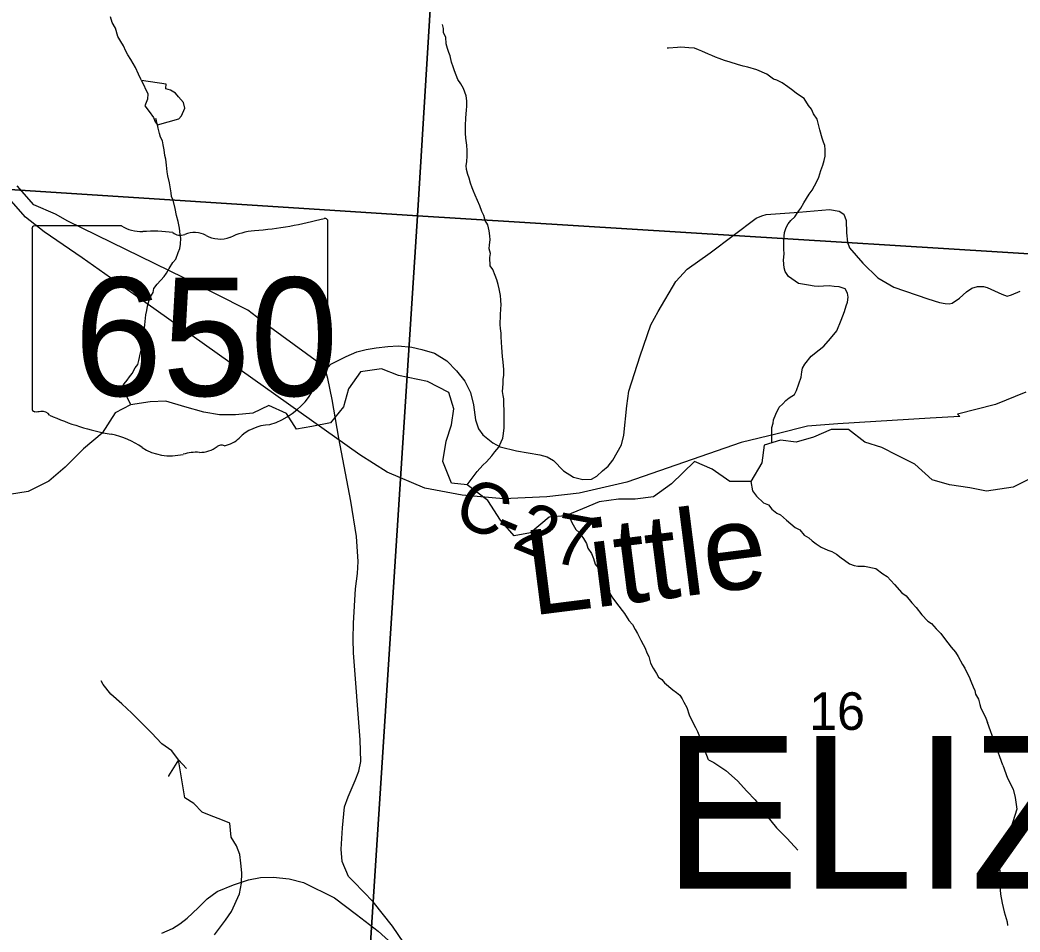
# Model space of a CAD drawing. Extents: x 0 to 82.7, y -0.2 to 22.
# Drawn here: x 4.26 to 5.374, y 16.567 to 17.584 of the extents above; entities that cross this region are included whole.
import ezdxf

# ---------------------------------------------------------------- set-up
doc = ezdxf.new("R2010")
doc.units = 0
for name, color, linetype in [('GM_X_County_Road', 7, 'Continuous'), ('GM_X_County_Road_Text', 7, 'Continuous'), ('GM_X_Minor_Lake', 7, 'Continuous'), ('GM_X_Minor_River', 7, 'Continuous'), ('GM_X_Minor_River_Text', 7, 'Continuous'), ('GM_X_Rail_Line', 7, 'Continuous'), ('GM_X_Section', 7, 'Continuous'), ('GM_X_Section_Text', 7, 'Continuous'), ('GM_X_State_Location', 7, 'Continuous'), ('GM_X_State_Route', 7, 'Continuous'), ('GM_X_State_Shield', 7, 'Continuous'), ('GM_X_Township_Text', 7, 'Continuous')]:
    doc.layers.add(name, color=color, linetype=linetype)

msp = doc.modelspace()

# ---------------------------------------------------------------- linework, layer by layer
at = {"layer": 'GM_X_County_Road'}
for points in [[(4.6002, 17.1934), (4.6062, 17.2003), (4.6231, 17.2085), (4.635, 17.2138), (4.6454, 17.2164), (4.6567, 17.2184), (4.6696, 17.2199), (4.681, 17.2204), (4.6965, 17.2189), (4.7075, 17.2166), (4.7217, 17.2124), (4.7354, 17.2039), (4.7463, 17.1927), (4.7554, 17.181), (4.7618, 17.1684), (4.765, 17.1547), (4.7674, 17.138), (4.7706, 17.128), (4.7756, 17.1213), (4.7867, 17.1125), (4.7946, 17.1081), (4.813, 17.1037), (4.8391, 17.099), (4.847, 17.0967), (4.8543, 17.0926), (4.8655, 17.0814), (4.8763, 17.0741), (4.8868, 17.0715), (4.8965, 17.0721), (4.9026, 17.0753), (4.9088, 17.0812), (4.9152, 17.0864), (4.9202, 17.0932), (4.9299, 17.1101), (4.9325, 17.121), (4.9357, 17.1538), (4.9381, 17.1702), (4.9506, 17.2093), (4.9625, 17.2439), (4.9707, 17.2587), (4.9905, 17.2923), (5.003, 17.3059), (5.0288, 17.3243), (5.08, 17.3628), (5.0862, 17.3654), (5.0909, 17.3669), (5.1274, 17.3695), (5.1617, 17.3726), (5.1723, 17.3708), (5.1775, 17.3672), (5.1801, 17.3604), (5.1806, 17.3464), (5.1816, 17.3361), (5.1839, 17.3298), (5.1987, 17.3125), (5.2156, 17.2964), (5.2332, 17.2858), (5.2712, 17.2731), (5.2842, 17.2688), (5.2905, 17.2677), (5.2948, 17.2673), (5.2981, 17.2682), (5.3063, 17.2736), (5.3143, 17.2806), (5.3202, 17.2848), (5.3266, 17.2865), (5.333, 17.2866), (5.3372, 17.2855), (5.3535, 17.278), (5.3594, 17.2759), (5.3644, 17.2773), (5.374, 17.2815)], [(4.4181, 16.5662), (4.4297, 16.5713), (4.4381, 16.5764), (4.4461, 16.5827), (4.4583, 16.5942), (4.4685, 16.6043), (4.4796, 16.6125), (4.4976, 16.6198), (4.5143, 16.6255), (4.528, 16.6281), (4.5421, 16.6283), (4.5599, 16.6266), (4.5758, 16.6226), (4.6103, 16.6054), (4.6347, 16.587), (4.6588, 16.5683), (4.6783, 16.5508)]]:
    msp.add_lwpolyline(points, dxfattribs=at)
at = {"layer": 'GM_X_Minor_Lake'}
for points in [[(4.3952, 17.5163), (4.4023, 17.5014), (4.4019, 17.4953), (4.3992, 17.4881), (4.4037, 17.4816), (4.4086, 17.4751), (4.4104, 17.4702), (4.4131, 17.4669)], [(4.4131, 17.4669), (4.437, 17.4734), (4.44, 17.4768), (4.4435, 17.4855), (4.442, 17.4916), (4.4364, 17.4981), (4.433, 17.5023), (4.4277, 17.5054), (4.4224, 17.5069), (4.4224, 17.5077), (4.4228, 17.5122), (4.3952, 17.5163)]]:
    msp.add_lwpolyline(points, dxfattribs=at)
at = {"layer": 'GM_X_Minor_River'}
for points in [[(4.3952, 17.5163), (4.3947, 17.5176), (4.3921, 17.5234), (4.3888, 17.5306), (4.3836, 17.5398), (4.3799, 17.5448), (4.378, 17.549), (4.3754, 17.5547), (4.3721, 17.5597), (4.3691, 17.5654), (4.3662, 17.5746), (4.3628, 17.5807), (4.3606, 17.5872)], [(4.7581, 17.0655), (4.7691, 17.0805), (4.7756, 17.0876), (4.7794, 17.0914), (4.7856, 17.0981), (4.789, 17.1023), (4.7933, 17.1075), (4.796, 17.1136), (4.7979, 17.1177), (4.7984, 17.1227), (4.7992, 17.1291), (4.7994, 17.1481), (4.7988, 17.1561), (4.7988, 17.1614), (4.7981, 17.1652), (4.7974, 17.1698), (4.7983, 17.1781), (4.7983, 17.1831), (4.7988, 17.188), (4.7988, 17.1941), (4.7982, 17.2025), (4.7975, 17.2085), (4.7965, 17.2188), (4.7958, 17.2306), (4.7959, 17.2348), (4.7952, 17.2397), (4.7949, 17.2443), (4.795, 17.2549), (4.7954, 17.2621), (4.7959, 17.2659), (4.7955, 17.2716), (4.7952, 17.2766), (4.7938, 17.2842), (4.7927, 17.2888), (4.7909, 17.2941), (4.7894, 17.2991), (4.7868, 17.3056), (4.7838, 17.3098), (4.7832, 17.3189), (4.784, 17.3235), (4.7825, 17.3288), (4.783, 17.333), (4.7838, 17.3387), (4.7831, 17.3432), (4.7824, 17.3486), (4.781, 17.3554), (4.778, 17.3604), (4.7765, 17.3657), (4.7743, 17.3703), (4.7721, 17.3764), (4.7669, 17.3886), (4.7651, 17.3928), (4.7636, 17.3967), (4.7618, 17.402), (4.7603, 17.4073), (4.7588, 17.4115), (4.7574, 17.4169), (4.7571, 17.4214), (4.7575, 17.4256), (4.7579, 17.4321), (4.758, 17.4382), (4.7577, 17.4442), (4.7567, 17.4518), (4.756, 17.4576), (4.7561, 17.4659), (4.7565, 17.4743), (4.7574, 17.4834), (4.7578, 17.4872), (4.7575, 17.4936), (4.7568, 17.4993), (4.7553, 17.5032), (4.7539, 17.5074), (4.7509, 17.5127), (4.7475, 17.5173), (4.7457, 17.5223), (4.7439, 17.5269), (4.7424, 17.5314), (4.7406, 17.5368), (4.7391, 17.5436), (4.7376, 17.5475), (4.7362, 17.552), (4.7347, 17.557), (4.7341, 17.5646), (4.7318, 17.5692), (4.7315, 17.5741), (4.7304, 17.5787)], [(5.0974, 17.1126), (5.0974, 17.1295), (5.099, 17.1344), (5.0994, 17.1382), (5.1017, 17.1443), (5.1056, 17.1522), (5.1095, 17.1559), (5.1129, 17.1597), (5.1168, 17.1627), (5.1225, 17.1664), (5.1248, 17.1709), (5.1299, 17.1857), (5.1307, 17.1914), (5.1316, 17.1956), (5.1343, 17.2001), (5.1412, 17.2091), (5.15, 17.2162), (5.1554, 17.2203), (5.1627, 17.2286), (5.1696, 17.2372), (5.1747, 17.249), (5.1782, 17.2588), (5.1802, 17.2652), (5.1817, 17.2694), (5.1822, 17.2747), (5.1815, 17.2793), (5.1789, 17.2839), (5.1724, 17.2862), (5.1667, 17.2867), (5.1611, 17.2875), (5.155, 17.2872), (5.1497, 17.2865), (5.1444, 17.287), (5.1383, 17.2882), (5.127, 17.2902), (5.1232, 17.2925), (5.116, 17.298), (5.1123, 17.3033), (5.1112, 17.3075), (5.1102, 17.3159), (5.111, 17.3231), (5.1107, 17.3284), (5.1108, 17.3387), (5.1113, 17.3467), (5.1133, 17.3523), (5.1156, 17.3565), (5.1187, 17.3602), (5.1229, 17.3644), (5.1264, 17.3696), (5.1298, 17.3741), (5.1329, 17.3798), (5.1391, 17.3896), (5.1422, 17.3941), (5.1449, 17.3987), (5.1476, 17.4036), (5.1496, 17.4085), (5.1519, 17.416), (5.1543, 17.4217), (5.1555, 17.427), (5.1567, 17.4319), (5.1568, 17.4395), (5.1564, 17.4437), (5.1549, 17.4475), (5.1535, 17.4521), (5.1509, 17.4613), (5.1477, 17.4731), (5.1439, 17.4792), (5.1417, 17.4842), (5.1383, 17.4884), (5.1335, 17.4961), (5.1248, 17.5019), (5.1207, 17.505), (5.1151, 17.5092), (5.109, 17.5135), (5.103, 17.5166), (5.0992, 17.5178), (5.0917, 17.5232), (5.0808, 17.5283), (5.0705, 17.5311), (5.0653, 17.5323), (5.0592, 17.5339), (5.0509, 17.5366), (5.0445, 17.5386), (5.0388, 17.5406), (5.0346, 17.5422), (5.0305, 17.5441), (5.0267, 17.5457), (5.0195, 17.5488), (5.0158, 17.5504), (5.0112, 17.5523), (5.0048, 17.5528), (4.9961, 17.5533), (4.9923, 17.553), (4.9824, 17.5523), (4.9807, 17.5522)], [(4.383, 17.1554), (4.3737, 17.1744), (4.376, 17.1782), (4.3795, 17.1823), (4.3818, 17.1861), (4.3849, 17.1899), (4.3884, 17.1959), (4.3911, 17.1997), (4.3923, 17.2042), (4.3942, 17.2129), (4.3958, 17.2178), (4.3955, 17.222), (4.3978, 17.2281), (4.3983, 17.2372), (4.3992, 17.244), (4.4, 17.255), (4.4012, 17.2599), (4.4021, 17.2649), (4.4044, 17.274), (4.4083, 17.28), (4.4091, 17.2845), (4.4126, 17.2891), (4.4206, 17.2977), (4.423, 17.3015), (4.4261, 17.3067), (4.4303, 17.3135), (4.4334, 17.3173), (4.4361, 17.3245), (4.4381, 17.329), (4.4389, 17.3339), (4.439, 17.3404), (4.4383, 17.3446), (4.4376, 17.3518), (4.4361, 17.359), (4.4343, 17.3659), (4.4329, 17.3735), (4.4304, 17.3827), (4.4289, 17.3869), (4.4282, 17.3911), (4.4264, 17.4021), (4.4246, 17.4101), (4.4239, 17.4143), (4.4232, 17.4219), (4.4225, 17.4287), (4.4214, 17.4326), (4.4204, 17.439), (4.4193, 17.4444), (4.4186, 17.4489), (4.4164, 17.4531), (4.4153, 17.4573), (4.4138, 17.4631), (4.4131, 17.4669), (4.412, 17.4711), (4.4113, 17.4739)], [(5.3849, 17.0725), (5.3663, 17.0631), (5.3363, 17.0587), (5.3178, 17.0622), (5.2954, 17.0657), (5.2761, 17.0711), (5.2565, 17.0887), (5.2372, 17.0983), (5.2198, 17.1071), (5.2009, 17.1133), (5.1828, 17.1274), (5.1635, 17.1272), (5.1437, 17.1189), (5.1243, 17.1133), (5.1069, 17.1153), (5.089, 17.1097), (5.0862, 17.09), (5.074, 17.0695), (5.0505, 17.0693), (5.0308, 17.0831), (5.0112, 17.0915), (4.9856, 17.0666), (4.9654, 17.0523), (4.9453, 17.0497), (4.9267, 17.0498), (4.9051, 17.0469), (4.8864, 17.039), (4.8674, 17.0311), (4.8492, 17.0297), (4.8286, 17.012), (4.8104, 17.0087), (4.795, 17.0262), (4.7811, 17.0483), (4.7581, 17.0655), (4.7406, 17.0675), (4.7309, 17.0915), (4.7345, 17.1142), (4.7407, 17.1324), (4.7431, 17.1503), (4.7375, 17.1685), (4.7137, 17.1808), (4.6815, 17.1874), (4.6626, 17.1951), (4.6391, 17.1914), (4.6257, 17.1725), (4.6202, 17.1524), (4.6057, 17.1347), (4.5852, 17.1306), (4.5681, 17.1276), (4.5568, 17.1452), (4.5372, 17.154), (4.5193, 17.1454), (4.5, 17.1436), (4.4821, 17.1437), (4.4647, 17.1468), (4.4435, 17.1526), (4.4223, 17.1588), (4.4049, 17.1581), (4.3832, 17.1548), (4.3661, 17.1458), (4.3515, 17.1231), (4.3306, 17.1057), (4.3103, 17.0853), (4.292, 17.0699), (4.2692, 17.0582), (4.2483, 17.0549)], [(5.074, 17.0695), (5.0757, 17.0591), (5.0802, 17.053), (5.0881, 17.0457), (5.0938, 17.0433), (5.0975, 17.0387), (5.1031, 17.0341), (5.1069, 17.0321), (5.1137, 17.0263), (5.1234, 17.0182), (5.1287, 17.0155), (5.1332, 17.0097), (5.1385, 17.0066), (5.1422, 17.0032), (5.1467, 17.0001), (5.1524, 16.9962), (5.1596, 16.9927), (5.1641, 16.9915), (5.1694, 16.9884), (5.1746, 16.9845), (5.1784, 16.9818), (5.1837, 16.9776), (5.189, 16.9756), (5.1931, 16.9752), (5.2007, 16.9751), (5.2132, 16.9726), (5.2211, 16.9665), (5.226, 16.9634), (5.2339, 16.9545), (5.2421, 16.9453), (5.247, 16.9418), (5.2534, 16.9341), (5.2582, 16.9291), (5.2646, 16.9207), (5.2713, 16.9138), (5.2751, 16.9111), (5.2803, 16.9053), (5.2856, 16.8999), (5.2897, 16.8945), (5.2972, 16.8849), (5.302, 16.8792), (5.305, 16.8742), (5.3098, 16.8654), (5.3124, 16.8612), (5.3143, 16.8574), (5.3173, 16.8516), (5.3191, 16.8467), (5.3217, 16.8406), (5.3235, 16.8364), (5.3243, 16.8325), (5.3276, 16.8268), (5.3291, 16.8207), (5.3301, 16.8169), (5.3331, 16.8112), (5.3357, 16.8058), (5.3377, 16.8007)], [(4.871, 17.0324), (4.8746, 17.0237), (4.8791, 17.016), (4.8828, 17.0126), (4.8877, 17.0057), (4.8911, 17.0003), (4.8925, 16.995), (4.8966, 16.9892), (4.8988, 16.9835), (4.9006, 16.9774), (4.9055, 16.9712), (4.9077, 16.964), (4.9107, 16.9598), (4.9129, 16.9521), (4.9155, 16.9472), (4.9192, 16.9407), (4.9244, 16.9338), (4.9334, 16.9222), (4.9382, 16.9146), (4.942, 16.91), (4.9453, 16.9046), (4.9476, 16.9), (4.9516, 16.8924), (4.9542, 16.8878), (4.9561, 16.8836), (4.9583, 16.8786), (4.9602, 16.8744), (4.9624, 16.8668), (4.9653, 16.8614), (4.969, 16.8553), (4.9713, 16.8515), (4.975, 16.8488), (4.978, 16.8449), (4.987, 16.8372), (4.9912, 16.8341), (4.9949, 16.8314), (4.9976, 16.8272), (4.9994, 16.8234), (5.0028, 16.8176), (5.0053, 16.8092), (5.0101, 16.7993), (5.0124, 16.7951), (5.0146, 16.7909), (5.0161, 16.7871), (5.0167, 16.7854)], [(4.4456, 16.7495), (4.4366, 16.7594), (4.4291, 16.7693), (4.4181, 16.777), (4.4065, 16.7892), (4.3952, 16.8003), (4.3847, 16.8114), (4.3734, 16.8217), (4.3613, 16.8324), (4.3527, 16.8431), (4.3505, 16.8473)], [(5.3548, 16.7532), (5.3377, 16.8007)], [(5.0268, 16.7594), (5.027, 16.7591), (5.0167, 16.7854)], [(4.4952, 16.6732), (4.4937, 16.6888), (4.4835, 16.6927), (4.4729, 16.697), (4.4627, 16.7008), (4.4537, 16.7107), (4.4435, 16.7169), (4.4366, 16.7594), (4.4255, 16.7413), (4.4255, 16.7405)], [(5.027, 16.7591), (5.0327, 16.7561), (5.0463, 16.7474), (5.0592, 16.736), (5.0694, 16.7243), (5.0788, 16.7148), (5.0898, 16.6992), (5.1026, 16.6833), (5.1143, 16.6716), (5.1262, 16.6586)], [(5.3548, 16.7532), (5.36, 16.7388), (5.3661, 16.7267), (5.3684, 16.7172), (5.3702, 16.7043)], [(5.3702, 16.7043), (5.3635, 16.683), (5.362, 16.6728), (5.3562, 16.6629), (5.3528, 16.6531), (5.3509, 16.6432), (5.3512, 16.63), (5.3512, 16.6193), (5.352, 16.6095), (5.3538, 16.5996), (5.3561, 16.5897), (5.3594, 16.5787), (5.3598, 16.5746)], [(4.4766, 16.5643), (4.4887, 16.5806), (4.4955, 16.5901), (4.5046, 16.6098), (4.5065, 16.6216), (4.5069, 16.6333), (4.5061, 16.644), (4.505, 16.6538), (4.5012, 16.6633), (4.4952, 16.6732)]]:
    msp.add_lwpolyline(points, dxfattribs=at)
at = {"layer": 'GM_X_Rail_Line'}
msp.add_lwpolyline([(5.3803, 17.1691), (5.3466, 17.155), (5.304, 17.1444), (5.3068, 17.1417), (5.2738, 17.1401), (5.1709, 17.1336), (5.1371, 17.1312), (5.1033, 17.1224), (5.0631, 17.1127), (4.936, 17.0685), (4.8829, 17.0564), (4.8467, 17.0524), (4.7985, 17.05), (4.7526, 17.054), (4.7108, 17.062), (4.669, 17.0797), (4.6384, 17.0991), (4.3859, 17.2785), (4.3294, 17.3185), (4.2868, 17.3475), (4.266, 17.3638), (4.2395, 17.3944)], dxfattribs=at)
at = {"layer": 'GM_X_Section'}
msp.add_lwpolyline([(3.7473, 18.3959), (3.7502, 18.459), (4.7658, 18.3936), (4.7026, 17.3656), (3.7019, 17.4301), (3.7258, 17.938)], dxfattribs=at)
for points in [[(4.7658, 18.3936), (5.7783, 18.3279), (5.7068, 17.3032), (4.7026, 17.3656)], [(3.7019, 17.4301), (4.7026, 17.3656), (4.6367, 16.3423), (3.6383, 16.3983)], [(4.7026, 17.3656), (5.7068, 17.3032), (5.6394, 16.2869), (4.6367, 16.3423)]]:
    msp.add_lwpolyline(points, close=True, dxfattribs=at)
at = {"layer": 'GM_X_State_Route'}
msp.add_lwpolyline([(4.7002, 16.5368), (4.6747, 16.5737), (4.6533, 16.6008), (4.6318, 16.6232), (4.6259, 16.6292), (4.6188, 16.6458), (4.6177, 16.6596), (4.6192, 16.6833), (4.6213, 16.7069), (4.6256, 16.718), (4.6334, 16.7362), (4.6372, 16.7465), (4.6397, 16.7574), (4.6387, 16.7816), (4.6316, 16.8785), (4.6309, 16.8938), (4.6316, 16.9116), (4.6337, 16.9496), (4.6358, 16.9667), (4.6368, 16.9803), (4.6347, 17.0082), (4.6284, 17.0475), (4.615, 17.1178), (4.6075, 17.1609), (4.6028, 17.1841), (4.6002, 17.1934), (4.5929, 17.2016), (4.538, 17.2419), (4.5139, 17.2604), (4.4423, 17.2965), (4.3131, 17.3594), (4.2994, 17.3671), (4.2752, 17.3777), (4.2569, 17.3988)], dxfattribs=at)
at = {"layer": 'GM_X_State_Shield'}
for p, q in [((4.3731, 17.3542), (4.2766, 17.3542)), ((4.6029, 17.2545), (4.6029, 17.3592)), ((4.2734, 17.3508), (4.2734, 17.1507)), ((4.6029, 17.2545), (4.6029, 17.2545))]:
    msp.add_line(p, q, dxfattribs=at)
for centre, major_axis, start_param, end_param in [((4.2771, 17.3512), (0.00382, 0), 1.712693, 3.28349), ((4.3961, 17.3775), (0.037, 0), 4.042523, 4.731795), ((4.4855, 17.6271), (0.3495, 0), 4.814394, 5.042369), ((4.5993, 17.3596), (0.00367, 0), 6.141152, 7.989035), ((4.4084, 17.2419), (0.133, 0), 1.404758, 1.657858), ((4.4386, 17.3523), (0.0107, 0), 3.836095, 5.185415), ((4.4543, 17.3291), (0.0222, 0), 0.950623, 2.079405), ((4.4829, 17.3609), (0.0267, 0), 4.081561, 5.145723), ((4.5301, 17.2931), (0.0703, 0), 1.699011, 2.107814), ((4.599, 17.2541), (0.00393, 0), 5.05454, 6.418171), ((4.6021, 17.2468), (0.00568, 0), 1.883978, 3.671073), ((4.566, 17.2336), (0.0341, 0), 5.934695, 6.695948), ((4.6161, 17.2107), (0.0248, 0), 2.387724, 3.262537), ((4.5051, 17.1974), (0.0874, 0), 5.101752, 6.440018), ((4.2772, 17.1502), (0.00385, 0), 3.00124, 4.508301), ((4.2777, 17.1707), (0.0294, 0), 4.665946, 4.897461), ((4.2838, 17.1391), (0.0106, 0), 0.519207, 1.627899), ((4.4176, 17.3189), (0.2524, 0), 4.195997, 4.488961), ((4.542, 17.0945), (0.0479, 0), 1.647645, 2.488434), ((4.3423, 17.0608), (0.079, 0), 0.823519, 1.323587), ((4.4604, 17.1232), (0.0267, 0), 4.691044, 5.507374), ((4.4845, 17.1038), (0.00752, 0), 1.147584, 2.315152), ((4.4813, 17.1313), (0.0282, 0), 4.937069, 5.64225), ((4.4277, 17.1381), (0.0501, 0), 4.026481, 4.996735), ((4.4567, 17.069), (0.0412, 0), 1.495662, 1.94098)]:
    msp.add_ellipse(centre, major_axis=major_axis, ratio=0.8, start_param=start_param, end_param=end_param, dxfattribs=at)

# ---------------------------------------------------------------- texts
at = {"layer": 'GM_X_County_Road_Text'}
for s, rotation, p in [('C', 335.5073, (4.7399, 17.0257)), ('2', 337.9096, (4.8063, 16.9963)), ('7', 349.5085, (4.8507, 16.9797)), ('-', 337.3378, (4.7842, 17.0056))]:
    msp.add_text(s, height=0.0568, rotation=rotation, dxfattribs=at).set_placement(p)
at = {"layer": 'GM_X_Minor_River_Text'}
msp.add_text('Little', height=0.09469, rotation=7.2298, dxfattribs=at).set_placement((4.8302, 16.9199))
at = {"layer": 'GM_X_Section_Text'}
msp.add_text('16', height=0.04186, rotation=0, dxfattribs=at).set_placement((5.1388, 16.7926))
at = {"layer": 'GM_X_State_Location'}
for s in ['s', 'r']:
    msp.add_text(s, height=0.000189, dxfattribs=at).set_placement((4.4344, 17.2374))
msp.add_text('650', height=0.000189, rotation=0, dxfattribs=at).set_placement((4.3676, 17.2237))
at = {"layer": 'GM_X_State_Shield'}
msp.add_text('650', height=0.13184, dxfattribs=at).set_placement((4.3203, 17.1648))
at = {"layer": 'GM_X_Township_Text'}
msp.add_text('ELIZABETH', height=0.17045, rotation=0, dxfattribs=at).set_placement((4.9762, 16.6155))

doc.saveas('drawing.dxf')
